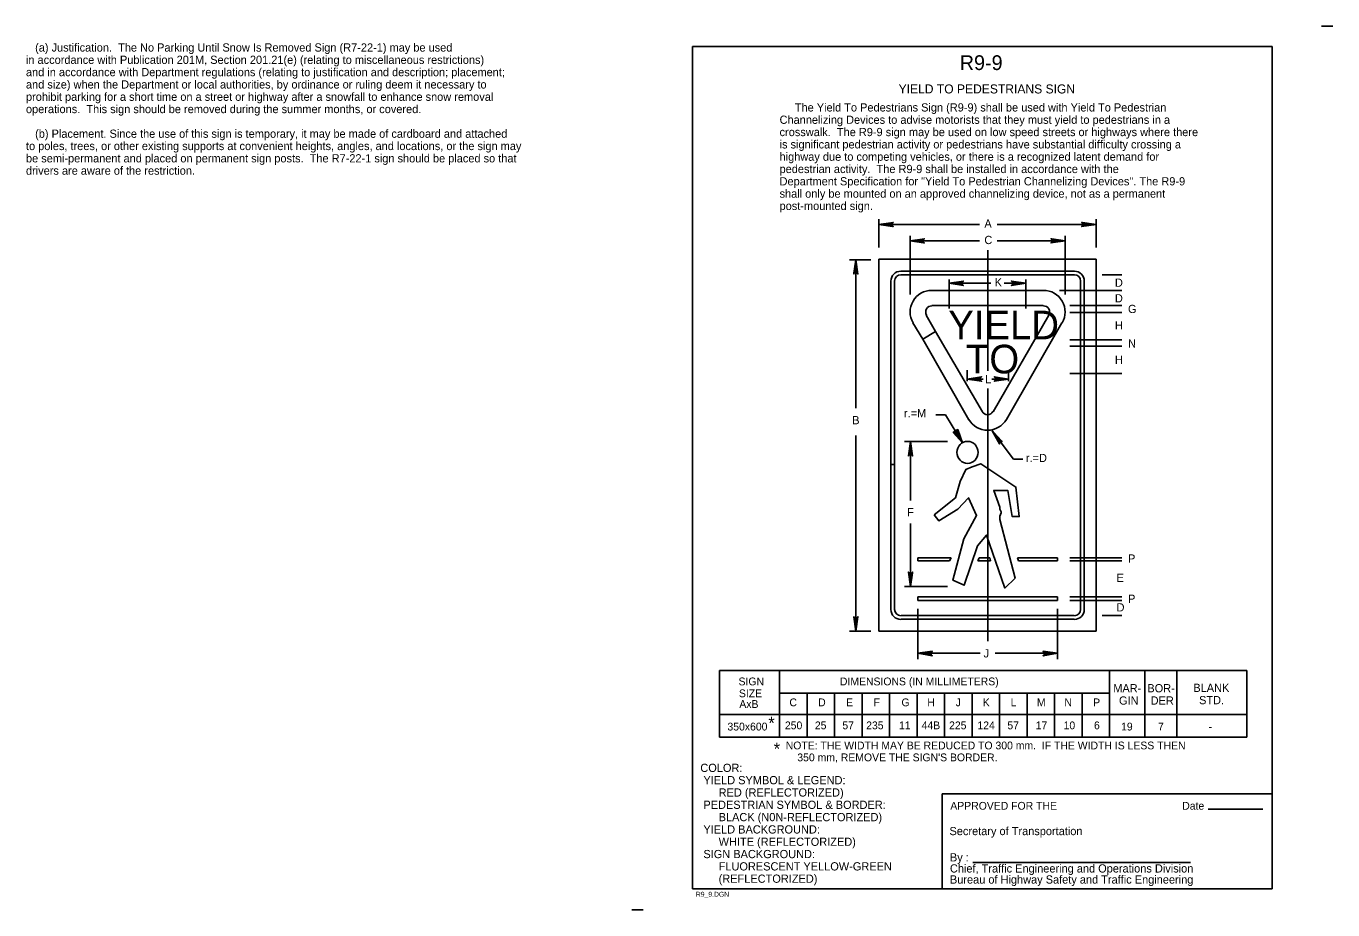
# Model space of a CAD drawing. Extents: x -0.203 to 0.195, y -0.006 to 0.263.
import ezdxf

# ---------------------------------------------------------------- set-up
doc = ezdxf.new("R2010")
doc.units = 0
for name, color, linetype in [('1', 7, 'Continuous'), ('11', 7, 'Continuous'), ('12', 7, 'Continuous'), ('2', 7, 'Continuous'), ('3', 7, 'Continuous')]:
    doc.layers.add(name, color=color, linetype=linetype)

msp = doc.modelspace()

# ---------------------------------------------------------------- linework, layer by layer
at = {"layer": '1'}
for p, q in [((0.195, 0.26275), (0.1915, 0.26275)), ((0.1765, 0.2565), (0, 0.2565)), ((0, 0.2565), (0, 0)), ((0.1765, 0), (0.1765, 0.2565)), ((0.076, 0.029), (0.1765, 0.029)), ((0.076, 0.029), (0.076, 0)), ((0.157, 0.02425), (0.173625, 0.02425)), ((0.085375, 0.008), (0.151625, 0.008)), ((0, 0), (0.1765, 0)), ((-0.015, -0.0063750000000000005), (-0.0185, -0.0063750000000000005))]:
    msp.add_line(p, q, dxfattribs=at)
at = {"layer": '11'}
for p, q in [((0.05675, 0.19175), (0.05675, 0.0785)), ((0.05675, 0.19175), (0.122875, 0.19175)), ((0.122875, 0.19175), (0.122875, 0.0785)), ((0.05675, 0.0785), (0.122875, 0.0785))]:
    msp.add_line(p, q, dxfattribs=at)
at = {"layer": '12'}
for p, q in [((0.0635, 0.18812500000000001), (0.11625, 0.18812500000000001)), ((0.060375, 0.12925), (0.060375, 0.18525)), ((0.0615, 0.18525), (0.0615, 0.12925)), ((0.11625, 0.187), (0.0635, 0.187)), ((0.11812500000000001, 0.085), (0.11812500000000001, 0.18525)), ((0.11925000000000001, 0.18525), (0.11925000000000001, 0.085)), ((0.10675, 0.18225), (0.072875, 0.18225)), ((0.072875, 0.177625), (0.10675, 0.177625)), ((0.067125, 0.172375), (0.070125, 0.167375)), ((0.074, 0.16975), (0.07112500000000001, 0.17475000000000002)), ((0.1085, 0.17475000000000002), (0.0915, 0.14525)), ((0.095625, 0.14300000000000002), (0.1125, 0.172375)), ((0.074, 0.16975), (0.070125, 0.167375)), ((0.070125, 0.167375), (0.074, 0.16975)), ((0.070125, 0.167375), (0.084125, 0.142875)), ((0.08825, 0.14525), (0.074, 0.16975)), ((0.060375, 0.12925), (0.0615, 0.12925)), ((0.0615, 0.12925), (0.060375, 0.12925)), ((0.060375, 0.085), (0.060375, 0.12925)), ((0.0615, 0.12925), (0.0615, 0.085)), ((0.068625, 0.099875), (0.068625, 0.100875)), ((0.068625, 0.100875), (0.07875, 0.100875)), ((0.07825, 0.099875), (0.068625, 0.099875)), ((0.07875, 0.100875), (0.07825, 0.099875)), ((0.08687500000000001, 0.099875), (0.08725000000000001, 0.100875)), ((0.09075, 0.099875), (0.08687500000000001, 0.099875)), ((0.08725000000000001, 0.100875), (0.0905, 0.100875)), ((0.0905, 0.100875), (0.09075, 0.099875)), ((0.111125, 0.100875), (0.099, 0.100875)), ((0.099, 0.100875), (0.09925, 0.099875)), ((0.09925, 0.099875), (0.111125, 0.099875)), ((0.111125, 0.099875), (0.111125, 0.100875)), ((0.111125, 0.089), (0.068625, 0.089)), ((0.068625, 0.089), (0.068625, 0.08787500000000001)), ((0.068625, 0.08787500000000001), (0.111125, 0.08787500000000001)), ((0.111125, 0.08787500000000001), (0.111125, 0.089)), ((0.0635, 0.08325), (0.11625, 0.08325)), ((0.11625, 0.082125), (0.0635, 0.082125))]:
    msp.add_line(p, q, dxfattribs=at)
msp.add_lwpolyline([(0.073625, 0.113875), (0.075, 0.112125), (0.08075, 0.115625), (0.084, 0.11912500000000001), (0.08650000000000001, 0.11375), (0.082625, 0.106625), (0.07925, 0.094), (0.08275, 0.0925), (0.08675000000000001, 0.1045), (0.0895, 0.10775), (0.095125, 0.091625), (0.09825, 0.094625), (0.093625, 0.1125), (0.093625, 0.1135), (0.094, 0.1145), (0.094, 0.114875), (0.093625, 0.115625), (0.093625, 0.11625), (0.09175, 0.121375), (0.096, 0.121375), (0.097375, 0.113375), (0.0995, 0.113375), (0.0985, 0.122375), (0.08775000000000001, 0.1295), (0.085125, 0.1285), (0.08325, 0.12775), (0.0815, 0.124125), (0.080125, 0.11912500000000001)], close=True, dxfattribs=at)
for centre, radius, start, end in [((0.06343367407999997, 0.18512338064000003), 0.0030124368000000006, 90, 180), ((0.11628190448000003, 0.18512338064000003), 0.0030124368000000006, 0, 90), ((0.06343367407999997, 0.18512338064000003), 0.0018874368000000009, 90, 180), ((0.11628190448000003, 0.18512338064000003), 0.0018874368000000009, 0, 90), ((0.07287085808, 0.17568619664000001), 0.006606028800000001, 90, 210.01589444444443), ((0.10684472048, 0.17568619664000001), 0.006606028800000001, 329.9841055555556, 90), ((0.07288307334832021, 0.17568619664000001), 0.001887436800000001, 89.99999999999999, 209.94100277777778), ((0.10683250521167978, 0.17568619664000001), 0.0018874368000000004, 330.0589972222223, 90.00000000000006), ((0.0898520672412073, 0.14629505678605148), 0.0018874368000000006, 210.108325, 330.0654916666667), ((0.0898520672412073, 0.14629505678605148), 0.006606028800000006, 210.108325, 330.0654916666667), ((0.06343367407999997, 0.08508923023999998), 0.0030124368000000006, 180, 270), ((0.06343367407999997, 0.08508923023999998), 0.0018874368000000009, 180, 270), ((0.11628190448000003, 0.08508923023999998), 0.0018874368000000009, 270, 0), ((0.11628190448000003, 0.08508923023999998), 0.0030124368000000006, 270, 0)]:
    msp.add_arc(centre, radius, start, end, dxfattribs=at)
msp.add_ellipse((0.0837448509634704, 0.1329399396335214), major_axis=(2.0580594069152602e-19, 0.003361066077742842), ratio=0.9570312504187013, dxfattribs=at)
at = {"layer": '3'}
for p, q in [((0.05675, 0.20400000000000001), (0.05675, 0.195375)), ((0.122875, 0.20400000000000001), (0.122875, 0.195375)), ((0.05675, 0.202375), (0.08737500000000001, 0.202375)), ((0.09275, 0.202375), (0.122875, 0.202375)), ((0.06625, 0.198875), (0.06625, 0.181)), ((0.06625, 0.197375), (0.08737500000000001, 0.197375)), ((0.09275, 0.197375), (0.1135, 0.197375)), ((0.1135, 0.198875), (0.1135, 0.181)), ((0.05425, 0.19162500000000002), (0.04775, 0.19162500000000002)), ((0.04975, 0.19162500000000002), (0.04975, 0.146375)), ((0.089875, 0.1945), (0.089875, 0.15775)), ((0.078125, 0.185625), (0.078125, 0.17675)), ((0.078125, 0.1845), (0.090875, 0.1845)), ((0.094875, 0.1845), (0.1015, 0.1845)), ((0.1015, 0.185625), (0.1015, 0.17675)), ((0.12475, 0.187), (0.13075, 0.187)), ((0.11175, 0.18225), (0.13075, 0.18225)), ((0.114875, 0.177625), (0.13075, 0.177625)), ((0.114875, 0.17550000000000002), (0.13075, 0.17550000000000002)), ((0.114875, 0.16725), (0.13075, 0.16725)), ((0.114875, 0.16525), (0.13075, 0.16525)), ((0.083625, 0.158), (0.083625, 0.154625)), ((0.083625, 0.15525), (0.0885, 0.15525)), ((0.091125, 0.15525), (0.09625, 0.15525)), ((0.09625, 0.15775), (0.09625, 0.154625)), ((0.114875, 0.157), (0.13075, 0.157)), ((0.089875, 0.152375), (0.089875, 0.0755)), ((0.077, 0.144375), (0.074125, 0.144375)), ((0.077, 0.144375), (0.08225, 0.135875)), ((0.09125, 0.1395), (0.09775, 0.130875)), ((0.09125, 0.1395), (0.0935, 0.136125)), ((0.04975, 0.138125), (0.04975, 0.0785)), ((0.0645, 0.13625), (0.077625, 0.13625)), ((0.066375, 0.13625), (0.066375, 0.11825000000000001)), ((0.09775, 0.130875), (0.100625, 0.130875)), ((0.066375, 0.11125), (0.066375, 0.092125)), ((0.114875, 0.100875), (0.13075, 0.100875)), ((0.114875, 0.099875), (0.13075, 0.099875)), ((0.0645, 0.092125), (0.077625, 0.092125)), ((0.114875, 0.089), (0.13075, 0.089)), ((0.114875, 0.08787500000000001), (0.13075, 0.08787500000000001)), ((0.068625, 0.08525), (0.068625, 0.07)), ((0.111125, 0.08525), (0.111125, 0.07)), ((0.12475, 0.08325), (0.13075, 0.08325)), ((0.05425, 0.0785), (0.04775, 0.0785)), ((0.068625, 0.07175000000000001), (0.08762500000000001, 0.07175000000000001)), ((0.111125, 0.07175000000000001), (0.092125, 0.07175000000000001)), ((0.00825, 0.0665), (0.16875, 0.0665)), ((0.00825, 0.0665), (0.00825, 0.04625)), ((0.0265, 0.0665), (0.0265, 0.04625)), ((0.127, 0.0665), (0.127, 0.04625)), ((0.13775, 0.066625), (0.13775, 0.046375)), ((0.1475, 0.0665), (0.1475, 0.04625)), ((0.16875, 0.0665), (0.16875, 0.04625)), ((0.127, 0.059625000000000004), (0.0265, 0.059625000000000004)), ((0.034875, 0.059625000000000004), (0.034875, 0.04625)), ((0.043250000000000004, 0.059625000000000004), (0.043250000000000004, 0.04625)), ((0.051625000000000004, 0.059625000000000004), (0.051625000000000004, 0.04625)), ((0.06, 0.059625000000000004), (0.06, 0.04625)), ((0.068375, 0.059625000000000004), (0.068375, 0.04625)), ((0.07675, 0.059625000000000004), (0.07675, 0.04625)), ((0.085125, 0.059625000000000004), (0.085125, 0.04625)), ((0.0935, 0.059625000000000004), (0.0935, 0.04625)), ((0.10187500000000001, 0.059625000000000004), (0.10187500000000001, 0.04625)), ((0.11025, 0.059625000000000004), (0.11025, 0.04625)), ((0.11862500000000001, 0.059625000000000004), (0.11862500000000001, 0.04625)), ((0.00825, 0.053125), (0.16875, 0.053125)), ((0.00825, 0.04625), (0.16875, 0.04625))]:
    msp.add_line(p, q, dxfattribs=at)
for points in [[(0.060875, 0.20175), (0.06075, 0.202125), (0.05675, 0.202375), (0.060875, 0.20175), (0.061125, 0.20175), (0.05675, 0.202375), (0.06075, 0.202625), (0.060875, 0.202875), (0.05675, 0.202375), (0.061125, 0.203), (0.060875, 0.202875)], [(0.11875000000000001, 0.203), (0.11875000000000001, 0.202625), (0.122875, 0.202375), (0.11875000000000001, 0.203), (0.11850000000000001, 0.203), (0.122875, 0.202375), (0.11875000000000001, 0.202125), (0.11875000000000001, 0.201875), (0.122875, 0.202375), (0.11850000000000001, 0.20175), (0.11875000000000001, 0.201875)], [(0.07037500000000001, 0.19675), (0.07025, 0.197125), (0.06625, 0.197375), (0.07037500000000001, 0.19675), (0.07062500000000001, 0.19675), (0.06625, 0.197375), (0.07025, 0.197625), (0.07037500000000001, 0.197875), (0.06625, 0.197375), (0.07062500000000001, 0.198), (0.07037500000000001, 0.197875)], [(0.109375, 0.198), (0.109375, 0.197625), (0.1135, 0.197375), (0.109375, 0.198), (0.109125, 0.198), (0.1135, 0.197375), (0.109375, 0.197125), (0.109375, 0.196875), (0.1135, 0.197375), (0.109125, 0.19675), (0.109375, 0.196875)], [(0.049125, 0.1875), (0.0495, 0.18762500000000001), (0.04975, 0.19162500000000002), (0.049125, 0.1875), (0.049125, 0.18725), (0.04975, 0.19162500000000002), (0.05, 0.18762500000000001), (0.05025, 0.1875), (0.04975, 0.19162500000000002), (0.050375, 0.18725), (0.05025, 0.1875)], [(0.08225, 0.183875), (0.082125, 0.18425), (0.078125, 0.1845), (0.08225, 0.183875), (0.0825, 0.18375), (0.078125, 0.1845), (0.082125, 0.184625), (0.08225, 0.184875), (0.078125, 0.1845), (0.0825, 0.185125), (0.08225, 0.184875)], [(0.097375, 0.185), (0.0975, 0.184625), (0.1015, 0.1845), (0.097375, 0.185), (0.097125, 0.185125), (0.1015, 0.1845), (0.0975, 0.18425), (0.097375, 0.184), (0.1015, 0.1845), (0.097125, 0.18375), (0.097375, 0.184)], [(0.08775000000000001, 0.15475), (0.08762500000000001, 0.155125), (0.083625, 0.15525), (0.08775000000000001, 0.15475), (0.088, 0.154625), (0.083625, 0.15525), (0.08762500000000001, 0.1555), (0.08775000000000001, 0.15575), (0.083625, 0.15525), (0.088, 0.156), (0.08775000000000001, 0.15575)], [(0.092125, 0.155875), (0.09225, 0.1555), (0.09625, 0.15525), (0.092125, 0.155875), (0.091875, 0.156), (0.09625, 0.15525), (0.09225, 0.155125), (0.092125, 0.154875), (0.09625, 0.15525), (0.091875, 0.154625), (0.092125, 0.154875)], [(0.079375, 0.139), (0.07975, 0.139125), (0.08225, 0.135875), (0.079375, 0.139), (0.079875, 0.139375), (0.08225, 0.135875), (0.080125, 0.139375), (0.08025, 0.13975), (0.08225, 0.135875), (0.08075, 0.139875), (0.08025, 0.13975)], [(0.0935, 0.13575), (0.093375, 0.136), (0.09125, 0.1395), (0.0935, 0.13575), (0.0935, 0.1355), (0.09125, 0.1395), (0.09375, 0.136375), (0.094, 0.136375), (0.09125, 0.1395), (0.09425, 0.13625), (0.094, 0.136375)], [(0.065875, 0.132125), (0.066125, 0.13225), (0.066375, 0.13625), (0.065875, 0.132125), (0.06575, 0.131875), (0.066375, 0.13625), (0.066625, 0.13225), (0.066875, 0.132125), (0.066375, 0.13625), (0.067, 0.131875), (0.066875, 0.132125)], [(0.067, 0.09625), (0.066625, 0.096125), (0.066375, 0.092125), (0.067, 0.09625), (0.067, 0.0965), (0.066375, 0.092125), (0.066125, 0.096125), (0.066, 0.09625), (0.066375, 0.092125), (0.06575, 0.0965), (0.066, 0.09625)], [(0.05025, 0.082625), (0.05, 0.0825), (0.04975, 0.0785), (0.05025, 0.082625), (0.050375, 0.082875), (0.04975, 0.0785), (0.0495, 0.0825), (0.04925, 0.082625), (0.04975, 0.0785), (0.049125, 0.082875), (0.04925, 0.082625)], [(0.07275, 0.07112500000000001), (0.072625, 0.07150000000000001), (0.068625, 0.07175000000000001), (0.07275, 0.07112500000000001), (0.073, 0.07100000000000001), (0.068625, 0.07175000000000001), (0.072625, 0.07187500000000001), (0.07275, 0.072125), (0.068625, 0.07175000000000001), (0.073, 0.072375), (0.07275, 0.072125)], [(0.107, 0.07112500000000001), (0.107125, 0.07150000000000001), (0.111125, 0.07175000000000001), (0.107, 0.07112500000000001), (0.10675, 0.07100000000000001), (0.111125, 0.07175000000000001), (0.107125, 0.07187500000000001), (0.107, 0.072125), (0.111125, 0.07175000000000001), (0.10675, 0.072375), (0.107, 0.072125)]]:
    msp.add_lwpolyline(points, dxfattribs=at)

# ---------------------------------------------------------------- texts
at = {"layer": '1'}
for s, height, p in [('R9-9', 0.0045000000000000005, (0.081375, 0.249375)), ('YIELD TO PEDESTRIANS SIGN', 0.00275025, (0.06275, 0.24225)), ('COLOR: ', 0.0024997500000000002, (0.002375, 0.035625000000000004)), (' YIELD SYMBOL & LEGEND:', 0.0024997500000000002, (0.002375, 0.031875)), ('      RED (REFLECTORIZED)', 0.0024997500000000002, (0.002375, 0.028125)), (' PEDESTRIAN SYMBOL & BORDER:', 0.0024997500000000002, (0.002375, 0.024375)), ('APPROVED FOR THE', 0.0023752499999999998, (0.0785, 0.024125)), ('Date ', 0.0023752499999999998, (0.149125, 0.024125)), ('      BLACK (N0N-REFLECTORIZED)', 0.0024997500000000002, (0.002375, 0.020625)), (' YIELD BACKGROUND:', 0.0024997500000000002, (0.002375, 0.016875)), ('Secretary of Transportation', 0.0024997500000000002, (0.07825, 0.016375)), ('      WHITE (REFLECTORIZED)', 0.0024997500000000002, (0.002375, 0.013125)), (' SIGN BACKGROUND:', 0.0024997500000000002, (0.002375, 0.009375)), ('      FLUORESCENT YELLOW-GREEN', 0.0024997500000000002, (0.002375, 0.005625)), ('By :', 0.0024997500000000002, (0.078375, 0.008375)), ('      (REFLECTORIZED)', 0.0024997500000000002, (0.002375, 0.001875)), ('Chief, Traffic Engineering and Operations Division', 0.0024997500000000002, (0.078375, 0.005)), ('Bureau of Highway Safety and Traffic Engineering', 0.0024997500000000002, (0.078375, 0.0016250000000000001)), ('R9_9.DGN', 0.0015, (0.001, -0.002375))]:
    msp.add_text(s, height=height, dxfattribs=at).set_placement(p)
at = {"layer": '12'}
for s, p in [('YIELD', (0.077875, 0.167375)), ('TO', (0.08325, 0.157))]:
    msp.add_text(s, height=0.008727, dxfattribs=at).set_placement(p)
at = {"layer": '2'}
for s, p in [('   (a) Justification.  The No Parking Until Snow Is Removed Sign (R7-22-1) may be used', (-0.203, 0.255)), ('in accordance with Publication 201M, Section 201.21(e) (relating to miscellaneous restrictions)', (-0.203, 0.25125000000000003)), ('and in accordance with Department regulations (relating to justification and description; placement;', (-0.203, 0.2475)), ('and size) when the Department or local authorities, by ordinance or ruling deem it necessary to', (-0.203, 0.24375)), ('operations.  This sign should be removed during the summer months, or covered.', (-0.203, 0.23625000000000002)), ('prohibit parking for a short time on a street or highway after a snowfall to enhance snow removal', (-0.203, 0.24)), ('   (b) Placement. Since the use of this sign is temporary, it may be made of cardboard and attached', (-0.203, 0.22875)), ('to poles, trees, or other existing supports at convenient heights, angles, and locations, or the sign may', (-0.203, 0.225)), ('be semi-permanent and placed on permanent sign posts.  The R7-22-1 sign should be placed so that', (-0.203, 0.22125)), ('drivers are aware of the restriction.', (-0.203, 0.2175))]:
    msp.add_text(s, height=0.0024997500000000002, dxfattribs=at).set_placement(p)
at = {"layer": '3'}
for s, height, p in [('     The Yield To Pedestrians Sign (R9-9) shall be used with Yield To Pedestrian', 0.0024997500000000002, (0.0265, 0.23675000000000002)), ('Channelizing Devices to advise motorists that they must yield to pedestrians in a', 0.0024997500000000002, (0.0265, 0.233)), ('crosswalk.  The R9-9 sign may be used on low speed streets or highways where there', 0.0024997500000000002, (0.0265, 0.22925)), ('is significant pedestrian activity or pedestrians have substantial difficulty crossing a', 0.0024997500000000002, (0.0265, 0.2255)), ('highway due to competing vehicles, or there is a recognized latent demand for', 0.0024997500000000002, (0.0265, 0.22175)), ('pedestrian activity.  The R9-9 shall be installed in accordance with the', 0.0024997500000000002, (0.0265, 0.218)), ('Department Specification for "Yield To Pedestrian Channelizing Devices". The R9-9', 0.0024997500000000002, (0.0265, 0.21425)), ('shall only be mounted on an approved channelizing device, not as a permanent', 0.0024997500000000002, (0.0265, 0.2105)), ('post-mounted sign.', 0.0024997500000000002, (0.0265, 0.20675000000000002)), ('A', 0.0024997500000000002, (0.088875, 0.201375)), ('C', 0.0024997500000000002, (0.088875, 0.196375)), ('K', 0.0024997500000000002, (0.092, 0.1835)), ('D', 0.0024997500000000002, (0.128625, 0.183375)), ('D', 0.0024997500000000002, (0.128625, 0.178625)), ('G', 0.0024997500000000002, (0.132625, 0.175375)), ('H', 0.0024997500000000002, (0.128625, 0.170375)), ('N', 0.0024997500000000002, (0.132625, 0.164875)), ('H', 0.0024997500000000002, (0.128625, 0.15987500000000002)), ('L', 0.0024997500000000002, (0.089125, 0.154)), ('B', 0.0024997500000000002, (0.048625, 0.14150000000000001)), ('r.=M', 0.0024997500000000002, (0.064375, 0.143625)), ('r.=D', 0.0024997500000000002, (0.1015, 0.13)), ('F', 0.0024997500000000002, (0.065375, 0.1135)), ('P', 0.0024997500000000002, (0.132625, 0.099375)), ('E', 0.0024997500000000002, (0.129125, 0.0935)), ('P', 0.0024997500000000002, (0.132625, 0.08712500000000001)), ('D', 0.0024997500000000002, (0.129125, 0.0845)), ('J', 0.0024997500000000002, (0.088625, 0.07050000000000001)), ('SIGN', 0.0023752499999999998, (0.014, 0.062)), ('DIMENSIONS (IN MILLIMETERS)', 0.0023752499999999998, (0.044875, 0.062)), ('SIZE', 0.0023752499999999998, (0.014125, 0.058375)), ('MAR-', 0.0024997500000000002, (0.128125, 0.059875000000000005)), ('BOR-', 0.0024997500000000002, (0.1385, 0.059875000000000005)), ('BLANK', 0.0024997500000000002, (0.1525, 0.06)), ('AxB', 0.0023752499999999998, (0.01425, 0.055125)), ('C', 0.0023752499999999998, (0.029500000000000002, 0.055625)), ('D', 0.0023752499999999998, (0.03825, 0.055625)), ('E', 0.0023752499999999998, (0.04675, 0.055625)), ('F', 0.0023752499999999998, (0.055125, 0.055625)), ('G', 0.0023752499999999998, (0.063625, 0.055625)), ('H', 0.0023752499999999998, (0.07150000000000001, 0.055625)), ('J', 0.0023752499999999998, (0.080125, 0.055625)), ('K', 0.0023752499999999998, (0.088375, 0.055625)), ('L', 0.0023752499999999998, (0.096875, 0.055625)), ('M', 0.0023752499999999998, (0.104875, 0.055625)), ('N', 0.0023752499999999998, (0.11325, 0.055625)), ('P', 0.0023752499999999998, (0.122, 0.055625)), ('GIN', 0.0024997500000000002, (0.129875, 0.056125)), ('DER', 0.0024997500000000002, (0.1395, 0.056125)), ('STD.', 0.0024997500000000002, (0.15425, 0.05625)), ('350x600', 0.0023752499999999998, (0.010625, 0.04825)), ('250', 0.0023752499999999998, (0.028125, 0.048625)), ('25', 0.0023752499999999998, (0.03725, 0.048625)), ('57', 0.0023752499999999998, (0.045625, 0.048625)), ('235', 0.0023752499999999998, (0.052875, 0.048625)), ('11', 0.0023752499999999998, (0.062875, 0.048625)), ('44B', 0.0023752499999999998, (0.06975, 0.048625)), ('225', 0.0023752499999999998, (0.078125, 0.048625)), ('124', 0.0023752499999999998, (0.08675000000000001, 0.048625)), ('57', 0.0023752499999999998, (0.095875, 0.048625)), ('17', 0.0023752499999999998, (0.1045, 0.048625)), ('10', 0.0023752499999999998, (0.113, 0.048625)), ('6', 0.0023752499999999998, (0.12225, 0.048625)), ('19', 0.0023752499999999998, (0.1305, 0.04825)), ('7', 0.0023752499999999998, (0.14175000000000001, 0.04825)), ('-', 0.0023752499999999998, (0.15712500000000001, 0.04825)), ('NOTE: THE WIDTH MAY BE REDUCED TO 300 mm.  IF THE WIDTH IS LESS THEN', 0.0023752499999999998, (0.028375, 0.0425)), ("    350 mm, REMOVE THE SIGN'S BORDER.", 0.0023752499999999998, (0.028375, 0.038875))]:
    msp.add_text(s, height=height, dxfattribs=at).set_placement(p)
for p in [(0.023125, 0.048625), (0.02475, 0.04075)]:
    msp.add_text('*', height=0.0037777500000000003, rotation=1, dxfattribs=at).set_placement(p)

doc.saveas('drawing.dxf')
